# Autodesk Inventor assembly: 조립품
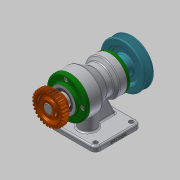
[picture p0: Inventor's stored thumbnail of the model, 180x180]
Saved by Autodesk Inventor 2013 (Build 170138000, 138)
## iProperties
Created: 2019-01
Part Number: 조립품
Document SubType Name: Assembly
Designer: Administrator
Author: Administrator
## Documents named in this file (15)
- C:\Users\Administrator\Documents\Inventor\490107V1027\조립품.iam
- C:\Users\Administrator\Documents\Inventor\490107V1027\본체.ipt
- C:\Users\Administrator\Documents\Inventor\490107V1027\V-벨트풀리.ipt
- C:\Users\Administrator\Documents\Inventor\490107V1027\뒤커버.ipt
- C:\Users\Administrator\Documents\Inventor\490107V1027\멈춤나사 M3.ipt
- C:\Users\Administrator\Documents\Inventor\490107V1027\베어링 6203.ipt
- C:\Users\Administrator\Documents\Inventor\490107V1027\베어링 6205.ipt
- C:\Users\Administrator\Documents\Inventor\490107V1027\볼트 M4.ipt
- C:\Users\Administrator\Documents\Inventor\490107V1027\스퍼기어.ipt
- C:\Users\Administrator\Documents\Inventor\490107V1027\앞커버.ipt
- C:\Users\Administrator\Documents\Inventor\490107V1027\오일 실 17 30 8.ipt
- C:\Users\Administrator\Documents\Inventor\490107V1027\오일 실 25 38 8.ipt
- C:\Users\Administrator\Documents\Inventor\490107V1027\축.ipt
- C:\Users\Administrator\Documents\Inventor\490107V1027\키 5 x 5 x 20.ipt
- C:\Users\Administrator\Documents\Inventor\490107V1027\키 6 x 6 x 18.ipt
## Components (1 placed, 1 different names)
1. V-벨트풀리:1
